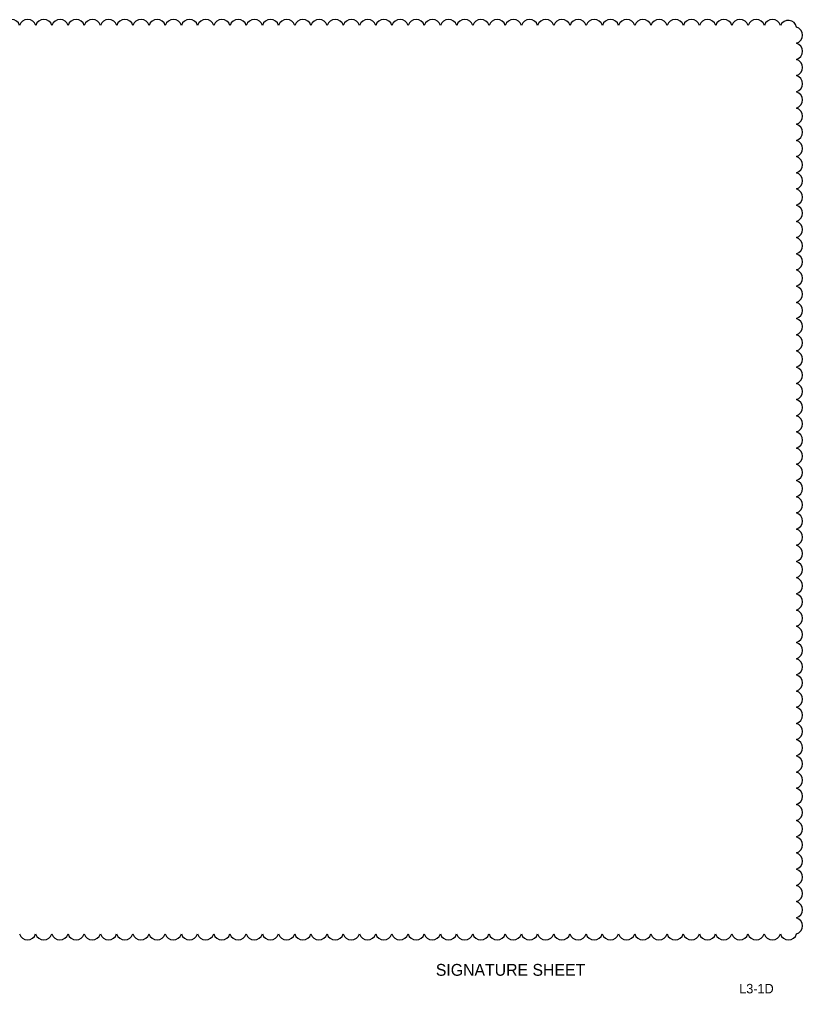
# Model space of a CAD drawing. Extents: x -811 to -795.3, y -2245.7 to -2235.4.
# Drawn here: x -803.6 to -795.32, y -2245.73 to -2235.44 of the extents above; entities that cross this region are included whole.
import ezdxf

# ---------------------------------------------------------------- set-up
doc = ezdxf.new("R2010")
doc.units = 0
for name, color, linetype in [('PlotBorder_dp', 7, 'Continuous'), ('ScratchEle_dp', 7, 'Continuous'), ('SheetLines_dp', 7, 'Continuous')]:
    doc.layers.add(name, color=color, linetype=linetype)

msp = doc.modelspace()

# ---------------------------------------------------------------- linework, layer by layer
at = {"layer": 'ScratchEle_dp'}
for centre, radius, start, end in [((-803.685, -2235.526), 0.0897, 17.5, 162.5), ((-803.514, -2235.526), 0.0897, 17.5, 162.5), ((-803.343, -2235.526), 0.0897, 17.5, 162.5), ((-803.172, -2235.526), 0.0897, 17.5, 162.5), ((-803.001, -2235.526), 0.0897, 17.5, 162.5), ((-802.83, -2235.526), 0.0897, 17.5, 162.5), ((-802.658, -2235.526), 0.0897, 17.5, 162.5), ((-802.487, -2235.526), 0.0897, 17.5, 162.5), ((-802.316, -2235.526), 0.0897, 17.5, 162.5), ((-802.145, -2235.526), 0.0897, 17.5, 162.5), ((-801.974, -2235.526), 0.0897, 17.5, 162.5), ((-801.803, -2235.526), 0.0897, 17.5, 162.5), ((-801.632, -2235.526), 0.0897, 17.5, 162.5), ((-801.461, -2235.526), 0.0897, 17.5, 162.5), ((-801.289, -2235.526), 0.0897, 17.5, 162.5), ((-801.118, -2235.526), 0.0897, 17.5, 162.5), ((-800.947, -2235.526), 0.0897, 17.5, 162.5), ((-800.776, -2235.526), 0.0897, 17.5, 162.5), ((-800.605, -2235.526), 0.0897, 17.5, 162.5), ((-800.434, -2235.526), 0.0897, 17.5, 162.5), ((-800.263, -2235.526), 0.0897, 17.5, 162.5), ((-800.092, -2235.526), 0.0897, 17.5, 162.5), ((-799.92, -2235.526), 0.0897, 17.5, 162.5), ((-799.749, -2235.526), 0.0897, 17.5, 162.5), ((-799.578, -2235.526), 0.0897, 17.5, 162.5), ((-799.407, -2235.526), 0.0897, 17.5, 162.5), ((-799.236, -2235.526), 0.0897, 17.5, 162.5), ((-799.065, -2235.526), 0.0897, 17.5, 162.5), ((-798.894, -2235.526), 0.0897, 17.5, 162.5), ((-798.723, -2235.526), 0.0897, 17.5, 162.5), ((-798.551, -2235.526), 0.0897, 17.5, 162.5), ((-798.38, -2235.526), 0.0897, 17.5, 162.5), ((-798.209, -2235.526), 0.0897, 17.5, 162.5), ((-798.038, -2235.526), 0.0897, 17.5, 162.5), ((-797.867, -2235.526), 0.0897, 17.5, 162.5), ((-797.696, -2235.526), 0.0897, 17.5, 162.5), ((-797.525, -2235.526), 0.0897, 17.5, 162.5), ((-797.354, -2235.526), 0.0897, 17.5, 162.5), ((-797.182, -2235.526), 0.0897, 17.5, 162.5), ((-797.011, -2235.526), 0.0897, 17.5, 162.5), ((-796.84, -2235.526), 0.0897, 17.5, 162.5), ((-796.669, -2235.526), 0.0897, 17.5, 162.5), ((-796.498, -2235.526), 0.0897, 17.5, 162.5), ((-796.327, -2235.526), 0.0897, 17.5, 162.5), ((-796.156, -2235.526), 0.0897, 17.5, 162.5), ((-795.985, -2235.526), 0.0897, 17.5, 162.5), ((-795.813, -2235.526), 0.0897, 17.5, 162.5), ((-795.642, -2235.526), 0.0897, 17.5, 162.5), ((-795.474, -2235.535), 0.0896, 11.7454, 156.7454), ((-795.414, -2235.602), 0.0897, 287.5, 72.5), ((-795.414, -2235.773), 0.0897, 287.5, 72.5), ((-795.414, -2235.944), 0.0897, 287.5, 72.5), ((-795.414, -2236.115), 0.0897, 287.5, 72.5), ((-795.414, -2236.287), 0.0897, 287.5, 72.5), ((-795.414, -2236.458), 0.0897, 287.5, 72.5), ((-795.414, -2236.629), 0.0897, 287.5, 72.5), ((-795.414, -2236.8), 0.0897, 287.5, 72.5), ((-795.414, -2236.971), 0.0897, 287.5, 72.5), ((-795.414, -2237.142), 0.0897, 287.5, 72.5), ((-795.414, -2237.313), 0.0897, 287.5, 72.5), ((-795.414, -2237.484), 0.0897, 287.5, 72.5), ((-795.414, -2237.656), 0.0897, 287.5, 72.5), ((-795.414, -2237.827), 0.0897, 287.5, 72.5), ((-795.414, -2237.998), 0.0897, 287.5, 72.5), ((-795.414, -2238.169), 0.0897, 287.5, 72.5), ((-795.414, -2238.34), 0.0897, 287.5, 72.5), ((-795.414, -2238.511), 0.0897, 287.5, 72.5), ((-795.414, -2238.682), 0.0897, 287.5, 72.5), ((-795.414, -2238.853), 0.0897, 287.5, 72.5), ((-795.414, -2239.025), 0.0897, 287.5, 72.5), ((-795.414, -2239.196), 0.0897, 287.5, 72.5), ((-795.414, -2239.367), 0.0897, 287.5, 72.5), ((-795.414, -2239.538), 0.0897, 287.5, 72.5), ((-795.414, -2239.709), 0.0897, 287.5, 72.5), ((-795.414, -2239.88), 0.0897, 287.5, 72.5), ((-795.414, -2240.051), 0.0897, 287.5, 72.5), ((-795.414, -2240.222), 0.0897, 287.5, 72.5), ((-795.414, -2240.394), 0.0897, 287.5, 72.5), ((-795.414, -2240.565), 0.0897, 287.5, 72.5), ((-795.414, -2240.736), 0.0897, 287.5, 72.5), ((-795.414, -2240.907), 0.0897, 287.5, 72.5), ((-795.414, -2241.078), 0.0897, 287.5, 72.5), ((-795.414, -2241.249), 0.0897, 287.5, 72.5), ((-795.414, -2241.42), 0.0897, 287.5, 72.5), ((-795.414, -2241.591), 0.0897, 287.5, 72.5), ((-795.414, -2241.762), 0.0897, 287.5, 72.5), ((-795.414, -2241.934), 0.0897, 287.5, 72.5), ((-795.414, -2242.105), 0.0897, 287.5, 72.5), ((-795.414, -2242.276), 0.0897, 287.5, 72.5), ((-795.414, -2242.447), 0.0897, 287.5, 72.5), ((-795.414, -2242.618), 0.0897, 287.5, 72.5), ((-795.414, -2242.789), 0.0897, 287.5, 72.5), ((-795.414, -2242.96), 0.0897, 287.5, 72.5), ((-795.414, -2243.131), 0.0897, 287.5, 72.5), ((-795.414, -2243.303), 0.0897, 287.5, 72.5), ((-795.414, -2243.474), 0.0897, 287.5, 72.5), ((-795.414, -2243.645), 0.0897, 287.5, 72.5), ((-795.414, -2243.816), 0.0897, 287.5, 72.5), ((-795.414, -2243.987), 0.0897, 287.5, 72.5), ((-795.414, -2244.158), 0.0897, 287.5, 72.5), ((-795.414, -2244.329), 0.0897, 287.5, 72.5), ((-795.414, -2244.5), 0.0897, 287.5, 72.5), ((-795.414, -2244.672), 0.0897, 287.5, 72.5), ((-795.414, -2244.843), 0.0897, 287.5, 72.5), ((-795.414, -2245.014), 0.0897, 287.5, 72.5), ((-803.515, -2245.072), 0.0897, 197.5, 342.5), ((-803.344, -2245.072), 0.0897, 197.5, 342.5), ((-803.173, -2245.072), 0.0897, 197.5, 342.5), ((-803.002, -2245.072), 0.0897, 197.5, 342.5), ((-802.831, -2245.072), 0.0897, 197.5, 342.5), ((-802.659, -2245.072), 0.0897, 197.5, 342.5), ((-802.488, -2245.072), 0.0897, 197.5, 342.5), ((-802.317, -2245.072), 0.0897, 197.5, 342.5), ((-802.146, -2245.072), 0.0897, 197.5, 342.5), ((-801.975, -2245.072), 0.0897, 197.5, 342.5), ((-801.804, -2245.072), 0.0897, 197.5, 342.5), ((-801.633, -2245.072), 0.0897, 197.5, 342.5), ((-801.462, -2245.072), 0.0897, 197.5, 342.5), ((-801.29, -2245.072), 0.0897, 197.5, 342.5), ((-801.119, -2245.072), 0.0897, 197.5, 342.5), ((-800.948, -2245.072), 0.0897, 197.5, 342.5), ((-800.777, -2245.072), 0.0897, 197.5, 342.5), ((-800.606, -2245.072), 0.0897, 197.5, 342.5), ((-800.435, -2245.072), 0.0897, 197.5, 342.5), ((-800.264, -2245.072), 0.0897, 197.5, 342.5), ((-800.093, -2245.072), 0.0897, 197.5, 342.5), ((-799.921, -2245.072), 0.0897, 197.5, 342.5), ((-799.75, -2245.072), 0.0897, 197.5, 342.5), ((-799.579, -2245.072), 0.0897, 197.5, 342.5), ((-799.408, -2245.072), 0.0897, 197.5, 342.5), ((-799.237, -2245.072), 0.0897, 197.5, 342.5), ((-799.066, -2245.072), 0.0897, 197.5, 342.5), ((-798.895, -2245.072), 0.0897, 197.5, 342.5), ((-798.724, -2245.072), 0.0897, 197.5, 342.5), ((-798.552, -2245.072), 0.0897, 197.5, 342.5), ((-798.381, -2245.072), 0.0897, 197.5, 342.5), ((-798.21, -2245.072), 0.0897, 197.5, 342.5), ((-798.039, -2245.072), 0.0897, 197.5, 342.5), ((-797.868, -2245.072), 0.0897, 197.5, 342.5), ((-797.697, -2245.072), 0.0897, 197.5, 342.5), ((-797.526, -2245.072), 0.0897, 197.5, 342.5), ((-797.355, -2245.072), 0.0897, 197.5, 342.5), ((-797.183, -2245.072), 0.0897, 197.5, 342.5), ((-797.012, -2245.072), 0.0897, 197.5, 342.5), ((-796.841, -2245.072), 0.0897, 197.5, 342.5), ((-796.67, -2245.072), 0.0897, 197.5, 342.5), ((-796.499, -2245.072), 0.0897, 197.5, 342.5), ((-796.328, -2245.072), 0.0897, 197.5, 342.5), ((-796.157, -2245.072), 0.0897, 197.5, 342.5), ((-795.986, -2245.072), 0.0897, 197.5, 342.5), ((-795.815, -2245.072), 0.0897, 197.5, 342.5), ((-795.643, -2245.072), 0.0897, 197.5, 342.5), ((-795.472, -2245.072), 0.0897, 197.5, 342.5)]:
    msp.add_arc(centre, radius, start, end, dxfattribs=at)

# ---------------------------------------------------------------- texts
at = {"layer": 'PlotBorder_dp'}
msp.add_text('       SIGNATURE SHEET         ', height=0.125, dxfattribs=at).set_placement((-799.525, -2245.541))
at = {"layer": 'SheetLines_dp'}
msp.add_text('L3-1D ', height=0.1, dxfattribs=at).set_placement((-795.993, -2245.727))

doc.saveas('drawing.dxf')
